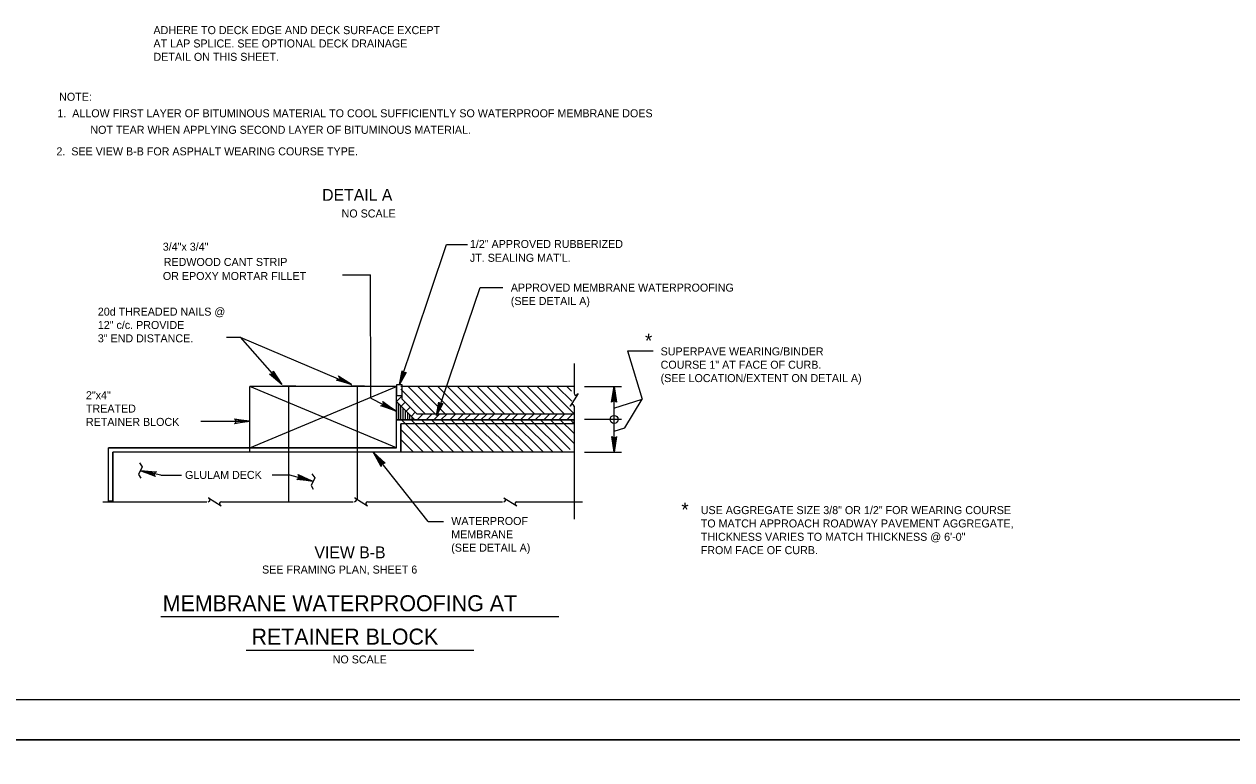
# Model space of a CAD drawing. Extents: x 638268 to 640277, y 295465 to 298435.
# Drawn here: x 638497.2 to 638949.9, y 296052 to 296327.6 of the extents above; entities that cross this region are included whole.
import ezdxf

# ---------------------------------------------------------------- set-up
doc = ezdxf.new("R2010")
doc.units = 0
for name, color, linetype in [('1', 7, 'Continuous'), ('2', 7, 'Continuous'), ('4', 7, 'Continuous'), ('62', 7, 'Continuous'), ('PLT-BNDY', 7, 'Continuous')]:
    doc.layers.add(name, color=color, linetype=linetype)

msp = doc.modelspace()

# ---------------------------------------------------------------- linework, layer by layer
at = {"layer": '1'}
for p, q in [((638578.15, 296210.3), (638593.71, 296192.66)), ((638578.15, 296210.3), (638619.95, 296192.66)), ((638723.33, 296205.26), (638732.97, 296205.26)), ((638723.33, 296205.26), (638728.84, 296187.07)), ((638581.79, 296168.84), (638636.8, 296191.81)), ((638636.8, 296168.84), (638581.79, 296191.81)), ((638593.84, 296192.1), (638598.98, 296192.1)), ((638596.41, 296148.68), (638596.41, 296192.1)), ((638619.61, 296192.1), (638624.75, 296192.1)), ((638622.18, 296149.63), (638622.18, 296192.1)), ((638718.17, 296183.74), (638728.84, 296187.07)), ((638722.33, 296176.41), (638728.84, 296187.07)), ((638721.05, 296179.43), (638707.19, 296179.43)), ((638718.35, 296175.17), (638722.33, 296176.41))]:
    msp.add_line(p, q, dxfattribs=at)
for points in [[(638717.65, 296186.28), (638718.05, 296186.48), (638718.35, 296191.81), (638717.65, 296186.28), (638717.41, 296185.99), (638718.35, 296191.81), (638718.61, 296186.49), (638719.01, 296186.29), (638718.35, 296191.81), (638719.27, 296185.99), (638719.01, 296186.29)], [(638576.26, 296179.52), (638576.46, 296179.12), (638581.79, 296178.82), (638576.26, 296179.52), (638575.97, 296179.76), (638581.79, 296178.82), (638576.47, 296178.56), (638576.27, 296178.16), (638581.79, 296178.82), (638575.97, 296177.9), (638576.27, 296178.16)], [(638719.04, 296172.78), (638718.64, 296172.57), (638718.35, 296167.24), (638719.04, 296172.78), (638719.28, 296173.06), (638718.35, 296167.24), (638718.08, 296172.57), (638717.69, 296172.76), (638718.35, 296167.24), (638717.42, 296173.06), (638717.69, 296172.76)]]:
    msp.add_lwpolyline(points, dxfattribs=at)
msp.add_circle((638718.35, 296179.52), 1.5, dxfattribs=at)
at = {"layer": '2'}
for p, q in [((638637.9, 296192.6), (638655.5, 296245.02)), ((638655.5, 296245.02), (638663.37, 296245.02)), ((638616.46, 296233.66), (638626.97, 296233.66)), ((638627.18, 296187.5), (638626.97, 296233.66)), ((638652.01, 296181.52), (638668.14, 296228.97)), ((638668.14, 296228.97), (638676.58, 296228.97)), ((638573.07, 296210.3), (638578.15, 296210.3)), ((638703.34, 296200.47), (638703.34, 296189.3)), ((638636.8, 296191.81), (638581.79, 296191.81)), ((638581.79, 296167.24), (638581.79, 296191.81)), ((638636.8, 296191.81), (638629.39, 296191.81)), ((638636.8, 296186.33), (638636.8, 296191.81)), ((638703.34, 296191.81), (638638.4, 296191.81)), ((638638.4, 296190.8), (638647.68, 296181.52)), ((638702.71, 296191.81), (638639.53, 296191.81)), ((638641.09, 296191.81), (638651.38, 296181.52)), ((638644.79, 296191.81), (638655.09, 296181.52)), ((638648.5, 296191.81), (638658.88, 296181.52)), ((638652.2, 296191.81), (638662.59, 296181.52)), ((638655.91, 296191.81), (638666.29, 296181.52)), ((638659.61, 296191.81), (638670, 296181.52)), ((638663.32, 296191.81), (638673.7, 296181.52)), ((638667.02, 296191.81), (638677.41, 296181.52)), ((638670.73, 296191.81), (638681.11, 296181.52)), ((638674.43, 296191.81), (638684.82, 296181.52)), ((638678.33, 296191.81), (638688.63, 296181.52)), ((638682.04, 296191.81), (638692.33, 296181.52)), ((638685.74, 296191.81), (638696.04, 296181.52)), ((638689.45, 296191.81), (638699.74, 296181.52)), ((638693.15, 296191.81), (638703.1, 296181.87)), ((638696.86, 296191.81), (638702.51, 296186.35)), ((638700.56, 296191.81), (638702.32, 296190.06)), ((638707.19, 296191.81), (638721.05, 296191.81)), ((638718.35, 296179.53), (638718.35, 296191.81)), ((638627.18, 296187.5), (638636.43, 296182.76)), ((638636.77, 296186.29), (638638.9, 296188.42)), ((638636.79, 296179.42), (638636.79, 296186.26)), ((638636.79, 296186.26), (638643.64, 296179.42)), ((638636.8, 296179.73), (638636.8, 296186.17)), ((638638.55, 296184.5), (638640.04, 296185.99)), ((638638.9, 296187.13), (638638.9, 296188.51)), ((638638.9, 296187.13), (638644.51, 296181.52)), ((638640.45, 296182.69), (638641.89, 296184.14)), ((638642.32, 296180.73), (638643.81, 296182.22)), ((638703.22, 296181.52), (638644.51, 296181.52)), ((638644.61, 296179.45), (638646.68, 296181.52)), ((638647.87, 296179.42), (638649.97, 296181.52)), ((638650.7, 296179.38), (638652.84, 296181.52)), ((638653.53, 296179.46), (638655.59, 296181.52)), ((638656.75, 296179.42), (638658.85, 296181.52)), ((638659.58, 296179.38), (638661.72, 296181.52)), ((638662.41, 296179.46), (638664.47, 296181.52)), ((638665.59, 296179.42), (638667.69, 296181.52)), ((638668.42, 296179.38), (638670.56, 296181.52)), ((638671.24, 296179.46), (638673.31, 296181.52)), ((638674.43, 296179.42), (638676.53, 296181.52)), ((638677.25, 296179.38), (638679.39, 296181.52)), ((638680.08, 296179.46), (638682.14, 296181.52)), ((638683.22, 296179.42), (638685.33, 296181.52)), ((638686.05, 296179.38), (638688.19, 296181.52)), ((638688.88, 296179.46), (638690.94, 296181.52)), ((638692.02, 296179.42), (638694.12, 296181.52)), ((638694.85, 296179.38), (638696.99, 296181.52)), ((638697.68, 296179.46), (638699.74, 296181.52)), ((638700.63, 296179.42), (638702.73, 296181.52)), ((638703.34, 296184.44), (638703.34, 296142.09)), ((638563.46, 296178.82), (638581.79, 296178.82)), ((638643.64, 296179.42), (638636.8, 296179.42)), ((638636.8, 296168.84), (638636.8, 296179.42)), ((638703.22, 296177.82), (638638.4, 296177.82)), ((638638.4, 296167.24), (638638.4, 296177.82)), ((638638.61, 296179.42), (638650.78, 296167.24)), ((638642.22, 296179.42), (638654.4, 296167.24)), ((638703.22, 296179.42), (638643.64, 296179.42)), ((638646.07, 296179.42), (638658.25, 296167.24)), ((638649.83, 296179.36), (638661.95, 296167.24)), ((638653.51, 296179.39), (638665.66, 296167.24)), ((638657.09, 296179.51), (638669.36, 296167.24)), ((638661.08, 296179.34), (638673.28, 296167.24)), ((638664.74, 296179.39), (638676.99, 296167.24)), ((638668.46, 296179.37), (638680.69, 296167.24)), ((638672.14, 296179.4), (638684.4, 296167.24)), ((638675.85, 296179.38), (638688.1, 296167.24)), ((638679.49, 296179.45), (638691.81, 296167.24)), ((638683.29, 296179.36), (638695.51, 296167.24)), ((638686.95, 296179.4), (638699.22, 296167.24)), ((638690.75, 296179.39), (638701.84, 296168.31)), ((638694.39, 296179.46), (638703.34, 296170.51)), ((638698.17, 296179.38), (638703.34, 296174.22)), ((638701.83, 296179.43), (638703.35, 296177.91)), ((638718.35, 296167.24), (638718.35, 296179.53)), ((638638.4, 296175.7), (638646.86, 296167.24)), ((638636.8, 296168.84), (638528.83, 296168.84)), ((638528.83, 296148.9), (638528.83, 296168.84)), ((638638.4, 296172.01), (638643.16, 296167.24)), ((638703.34, 296167.24), (638530.43, 296167.24)), ((638530.43, 296148.9), (638530.43, 296167.24)), ((638636.8, 296167.24), (638581.79, 296167.24)), ((638707.19, 296167.24), (638721.05, 296167.24)), ((638590.16, 296158.79), (638596.69, 296158.79)), ((638548.46, 296158.6), (638556.22, 296158.6)), ((638526.68, 296148.68), (638565.7, 296148.68)), ((638571.11, 296148.68), (638620.57, 296148.68)), ((638626.02, 296148.61), (638676.46, 296148.61)), ((638681.8, 296148.61), (638706.48, 296148.61)), ((638648.57, 296141.28), (638654.41, 296141.28)), ((638548.36, 296105.65), (638697.57, 296105.65)), ((638580.4, 296093.09), (638665.7, 296093.09)), ((639261.46, 296074.46), (638475.46, 296074.46))]:
    msp.add_line(p, q, dxfattribs=at)
for points in [[(638640.1, 296197.06), (638639.55, 296196.98), (638637.9, 296192.6), (638640.1, 296197.06), (638640.37, 296197.09), (638637.9, 296192.6), (638639.13, 296197.07), (638638.94, 296197.46), (638637.9, 296192.6), (638638.9, 296197.73), (638638.94, 296197.46)], [(638653.96, 296185.43), (638653.57, 296185.23), (638651.81, 296180.94), (638653.96, 296185.43), (638654.15, 296185.43), (638651.81, 296180.94), (638652.98, 296185.43), (638652.79, 296185.62), (638651.81, 296180.94), (638652.59, 296186.01), (638652.79, 296185.62)], [(638704.66, 296188.94), (638704.85, 296189.24), (638701.83, 296184.43), (638702.03, 296184.75)], [(638566.54, 296150.01), (638566.24, 296150.2), (638571.05, 296147.17), (638570.73, 296147.38)], [(638621.41, 296150.01), (638621.11, 296150.2), (638625.92, 296147.17), (638625.6, 296147.38)], [(638677.3, 296149.94), (638677, 296150.12), (638681.81, 296147.1), (638681.49, 296147.3)]]:
    msp.add_lwpolyline(points, dxfattribs=at)
for centre, start, end in [((638704.05, 296189.3), 180, 330), ((638702.63, 296184.38), 5.3286, 147.8672), ((638566.18, 296149.4), 270, 60), ((638621.05, 296149.4), 270, 60), ((638676.94, 296149.32), 270, 60), ((638571.11, 296147.98), 95.3286, 237.8672), ((638625.98, 296147.98), 95.3286, 237.8672), ((638681.86, 296147.9), 95.3286, 237.8672)]:
    msp.add_arc(centre, 0.71, start, end, dxfattribs=at)
at = {"layer": '62'}
for p, q in [((638637.59, 296179.42), (638637.59, 296185.47)), ((638638.43, 296179.42), (638638.43, 296184.63)), ((638639.27, 296179.42), (638639.27, 296183.79)), ((638640.11, 296179.42), (638640.11, 296182.95)), ((638640.95, 296179.42), (638640.95, 296182.11)), ((638641.79, 296179.42), (638641.79, 296181.27)), ((638642.64, 296179.42), (638642.64, 296180.41)), ((638648.57, 296141.28), (638628.16, 296167.09)), ((638548.46, 296158.6), (638540.88, 296160.24)), ((638596.69, 296158.79), (638605.21, 296156.36))]:
    msp.add_line(p, q, dxfattribs=at)
for points in [[(638590.58, 296197.28), (638590.41, 296196.86), (638593.71, 296192.66), (638590.58, 296197.28), (638590.57, 296197.65), (638593.71, 296192.66), (638590, 296196.49), (638589.57, 296196.38), (638593.71, 296192.66), (638589.17, 296196.43), (638589.57, 296196.38)], [(638615.19, 296195.57), (638615.21, 296195.12), (638619.95, 296192.66), (638615.19, 296195.57), (638615.03, 296195.91), (638619.95, 296192.66), (638614.99, 296194.61), (638614.65, 296194.33), (638619.95, 296192.66), (638614.26, 296194.21), (638614.65, 296194.33)], [(638631.82, 296185.9), (638631.82, 296185.45), (638636.43, 296182.76), (638631.82, 296185.9), (638631.68, 296186.25), (638636.43, 296182.76), (638631.57, 296184.95), (638631.21, 296184.69), (638636.43, 296182.76), (638630.83, 296184.59), (638631.21, 296184.69)], [(638540.39, 296163.26), (638541.46, 296161.8), (638540.1, 296158.88), (638540.88, 296157.52)], [(638631.05, 296162.31), (638631.24, 296162.73), (638628.16, 296167.09), (638631.05, 296162.31), (638631.04, 296161.94), (638628.16, 296167.09), (638631.67, 296163.07), (638632.1, 296163.17), (638628.16, 296167.09), (638632.5, 296163.1), (638632.1, 296163.17)], [(638546.14, 296158.39), (638546.02, 296158.83), (638540.88, 296160.24), (638546.14, 296158.39), (638546.37, 296158.09), (638540.88, 296160.24), (638546.14, 296159.37), (638546.41, 296159.72), (638540.88, 296160.24), (638546.76, 296159.91), (638546.41, 296159.72)], [(638600.08, 296158.55), (638600.16, 296158.11), (638605.21, 296156.36), (638600.08, 296158.55), (638599.87, 296158.86), (638605.21, 296156.36), (638600.02, 296157.57), (638599.72, 296157.24), (638605.21, 296156.36), (638599.36, 296157.07), (638599.72, 296157.24)], [(638605.01, 296159.08), (638606.08, 296157.62), (638604.72, 296154.7), (638605.5, 296153.34)]]:
    msp.add_lwpolyline(points, dxfattribs=at)
for points in [[(638636.73, 296188.51), (638638.9, 296188.51), (638638.9, 296192.54), (638636.73, 296192.54)], [(638636.79, 296186.26), (638636.79, 296179.42), (638643.64, 296179.42)], [(638703.22, 296179.42), (638703.22, 296177.82), (638638.4, 296177.82), (638638.4, 296167.24), (638530.43, 296167.24), (638530.43, 296148.9), (638528.83, 296148.9), (638528.83, 296168.84), (638636.8, 296168.84), (638636.79, 296179.42)]]:
    msp.add_lwpolyline(points, close=True, dxfattribs=at)
at = {"layer": 'PLT-BNDY'}
for points in [[(638435.46, 296653.46), (639276.46, 296653.46), (639276.46, 296059.46), (638435.46, 296059.46)], [(638435.46, 296059.46), (639276.46, 296059.46), (639276.46, 295465.46), (638435.46, 295465.46)]]:
    msp.add_lwpolyline(points, close=True, dxfattribs=at)

# ---------------------------------------------------------------- texts
at = {"layer": '1'}
for p in [(638729.91, 296206.46), (638743.56, 296143.14)]:
    msp.add_text('*', height=5.18, dxfattribs=at).set_placement(p)
at = {"layer": '2'}
for s, height, p in [('3/4"x 3/4"', 3, (638549.14, 296242.76)), ('1/2" APPROVED RUBBERIZED', 3, (638664.27, 296243.77)), ("JT. SEALING MAT'L.", 3, (638664.27, 296238.59)), ('REDWOOD CANT STRIP', 3, (638549.51, 296237.03)), ('OR EPOXY MORTAR FILLET', 3, (638549.18, 296231.77)), ('APPROVED MEMBRANE WATERPROOFING', 3, (638679.61, 296227.41)), ('(SEE DETAIL A)', 3, (638679.61, 296222.41)), ('20d THREADED NAILS @', 3, (638524.79, 296218.41)), ('12" c/c. PROVIDE', 3, (638524.79, 296213.41)), ('3" END DISTANCE.', 3, (638524.79, 296208.41)), ('SUPERPAVE WEARING/BINDER', 3, (638735.77, 296203.52)), ('COURSE 1" AT FACE OF CURB.', 3, (638735.77, 296198.52)), ('(SEE LOCATION/EXTENT ON DETAIL A)', 3, (638735.77, 296193.51)), ('2"x4"', 3, (638520.34, 296187.09)), ('TREATED', 3, (638520.34, 296182.09)), ('RETAINER BLOCK', 3, (638520.34, 296177.09)), ('GLULAM DECK', 3, (638557.49, 296157.22)), ('USE AGGREGATE SIZE 3/8" OR 1/2" FOR WEARING COURSE', 3, (638750.82, 296144.04)), ('WATERPROOF', 3, (638657.29, 296139.96)), ('TO MATCH APPROACH ROADWAY PAVEMENT AGGREGATE,', 3, (638750.82, 296139.04)), ('MEMBRANE', 3, (638657.29, 296134.96)), ('THICKNESS VARIES TO MATCH THICKNESS @ 6\'-0"', 3, (638750.82, 296134.04)), ('(SEE DETAIL A)', 3, (638657.29, 296129.96)), ('FROM FACE OF CURB.', 3, (638750.82, 296129.04)), ('MEMBRANE WATERPROOFING AT', 6, (638549.12, 296107.64)), ('RETAINER BLOCK', 6, (638582.4, 296095.13))]:
    msp.add_text(s, height=height, dxfattribs=at).set_placement(p)
at = {"layer": '4'}
for s, height, p in [('ADHERE TO DECK EDGE AND DECK SURFACE EXCEPT', 3, (638545.65, 296323.9)), ('AT LAP SPLICE. SEE OPTIONAL DECK DRAINAGE ', 3, (638545.65, 296318.9)), ('DETAIL ON THIS SHEET.', 3, (638545.65, 296313.9)), ('NOTE:', 3, (638510.29, 296298.93)), ('1.  ALLOW FIRST LAYER OF BITUMINOUS MATERIAL TO COOL SUFFICIENTLY SO WATERPROOF MEMBRANE DOES ', 3, (638509.63, 296292.74)), ('NOT TEAR WHEN APPLYING SECOND LAYER OF BITUMINOUS MATERIAL.', 3, (638522, 296286.55)), ('2.  SEE VIEW B-B FOR ASPHALT WEARING COURSE TYPE.', 3, (638509.28, 296278.47)), ('DETAIL A', 4.429, (638608.88, 296261.45)), ('NO SCALE', 3, (638616.18, 296255.19)), ('VIEW B-B', 4.429, (638606, 296127.49)), ('SEE FRAMING PLAN, SHEET 6', 3, (638586.35, 296121.76)), ('NO SCALE', 3, (638612.84, 296088.09))]:
    msp.add_text(s, height=height, dxfattribs=at).set_placement(p)

doc.saveas('drawing.dxf')
